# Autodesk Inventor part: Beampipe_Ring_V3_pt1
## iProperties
Shininess: 64.0
Length Units: 11269
Angle Units: 11279
Time Units: 11290
Mass Units: 11283
Length Display Precision: 3
Angle Display Precision: 2
Compacted: True
Part Number: Beampipe_Ring_V3_pt1
Document SubType Name: Modeling
Created: 2004-08
Designer: John Blackburn
Manufacturer: Standard
Standards Organization: Custom
Material: Aluminum-6061
Density: 0.0
Volumn: 0.0
Area: 0.0
PropertySet Name: Model Information
Control State: 0
Master: False
Checked Out: False
Author: John Blackburn
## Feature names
1. Extrusion1
2. Extrusion3
3. Split1
4. Hole6
5. Hole7
6. Hole10
7. Extrusion8
8. Extrusion9
9. Extrusion10
10. Hole11
